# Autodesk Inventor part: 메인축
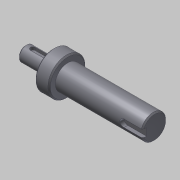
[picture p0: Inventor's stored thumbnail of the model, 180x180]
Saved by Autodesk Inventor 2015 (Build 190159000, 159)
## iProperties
Created: 2018-09
Part Number: 메인축
Document SubType Name: Modeling
Density: 1 g/cm^3
Material: 강철, 연강
Appearance: 강철
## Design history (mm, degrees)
sketch "스케치1"
  geometry: L1 (34.997, -37.5)-(34.997, -77.5) reference; L2 (46.5, -38.401)-(46.5, -76.599) reference; L3 (12.497, -57.5)-(116.5, -57.5); L4 (12.497, -63.5)-(34.997, -63.5); L5 (34.997, -72.5)-(46.5, -72.5); L6 (46.5, -67.5)-(116.5, -67.5); L7 (116.5, -67.5)-(116.5, -57.5); L8 (12.497, -63.5)-(12.497, -57.5); 2 further points
  constraints: 12 end point, 5 point on line, 4 perpendicular, 1 midpoint, 1 parallel
  dimensions: "d0" = 20 diameter of L6 L3; "d1" = 30 diameter of L5 L3; "d2" = 22.5 distance of L4.start L4.end; "d3" = 70 distance of L6.start L6.end; "d5" = 12 diameter of L4 L3
revolve "회전1" sketch "스케치1" stored, may be unused: angle "d4" = 90 deg
chamfer "모따기1" distance "d6" = 1; stored, may be unused: second distance "d7" = 2, angle "d8" = 45 deg
node "작업 평면1"
sketch "스케치2"
  geometry: L1 (-11.25, -5)-(-11.25, 5) reference; L2 (-5.25, 2)-(4.75, 2); L3 (4.75, -2)-(-5.25, -2); A1 r 2 centre (4.75, 0) between (4.75, -2) and (4.75, 2); A2 r 2 centre (-5.25, 0) between (-5.25, 2) and (-5.25, -2); 2 further points
  constraints: 4 end point, 4 point on circle, 4 tangent, 2 centre point, 1 horizontal alignment, 1 midpoint, 1 parallel, 1 perpendicular
  dimensions: "d9" = 4 distance between parallel lines of L3 L2; "d10" = 14 dimension on A1 A2; "d11" = 4 distance edge to line of A2 L1
extrude "돌출1" cut sketch "스케치2" distance "d12" = 2.5; taper "d13" = 0 deg
node "작업 평면2"
sketch "스케치3"
  geometry: L1 (35, 9)-(35, -9) reference; L2 (35, 3)-(20, 3); L3 (20, -3)-(35, -3); A1 r 3 centre (20, 0) between (20, 3) and (20, -3); 2 further points
  constraints: 4 end point, 2 perpendicular, 2 point on circle, 2 point on line, 2 tangent, 1 centre point, 1 horizontal alignment, 1 midpoint
  dimensions: "d14" = 6 distance between parallel lines of L3 L2; "d15" = 18 dimension on A1 L1
extrude "돌출2" cut sketch "스케치3" distance "d16" = 3.5; taper "d17" = 0 deg
node "솔리드1"
node "참조1"
node "참조2"
